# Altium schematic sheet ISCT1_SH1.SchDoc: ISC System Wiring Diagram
size B; DrawnBy: Filiberto Clara; Engineer: Filiberto Clara; Organization: LIGO Laboratory; Address1: California Institute of Technology; Address2: Massachusetts Institute of Technology; SheetNumber: 24; SheetTotal: 39
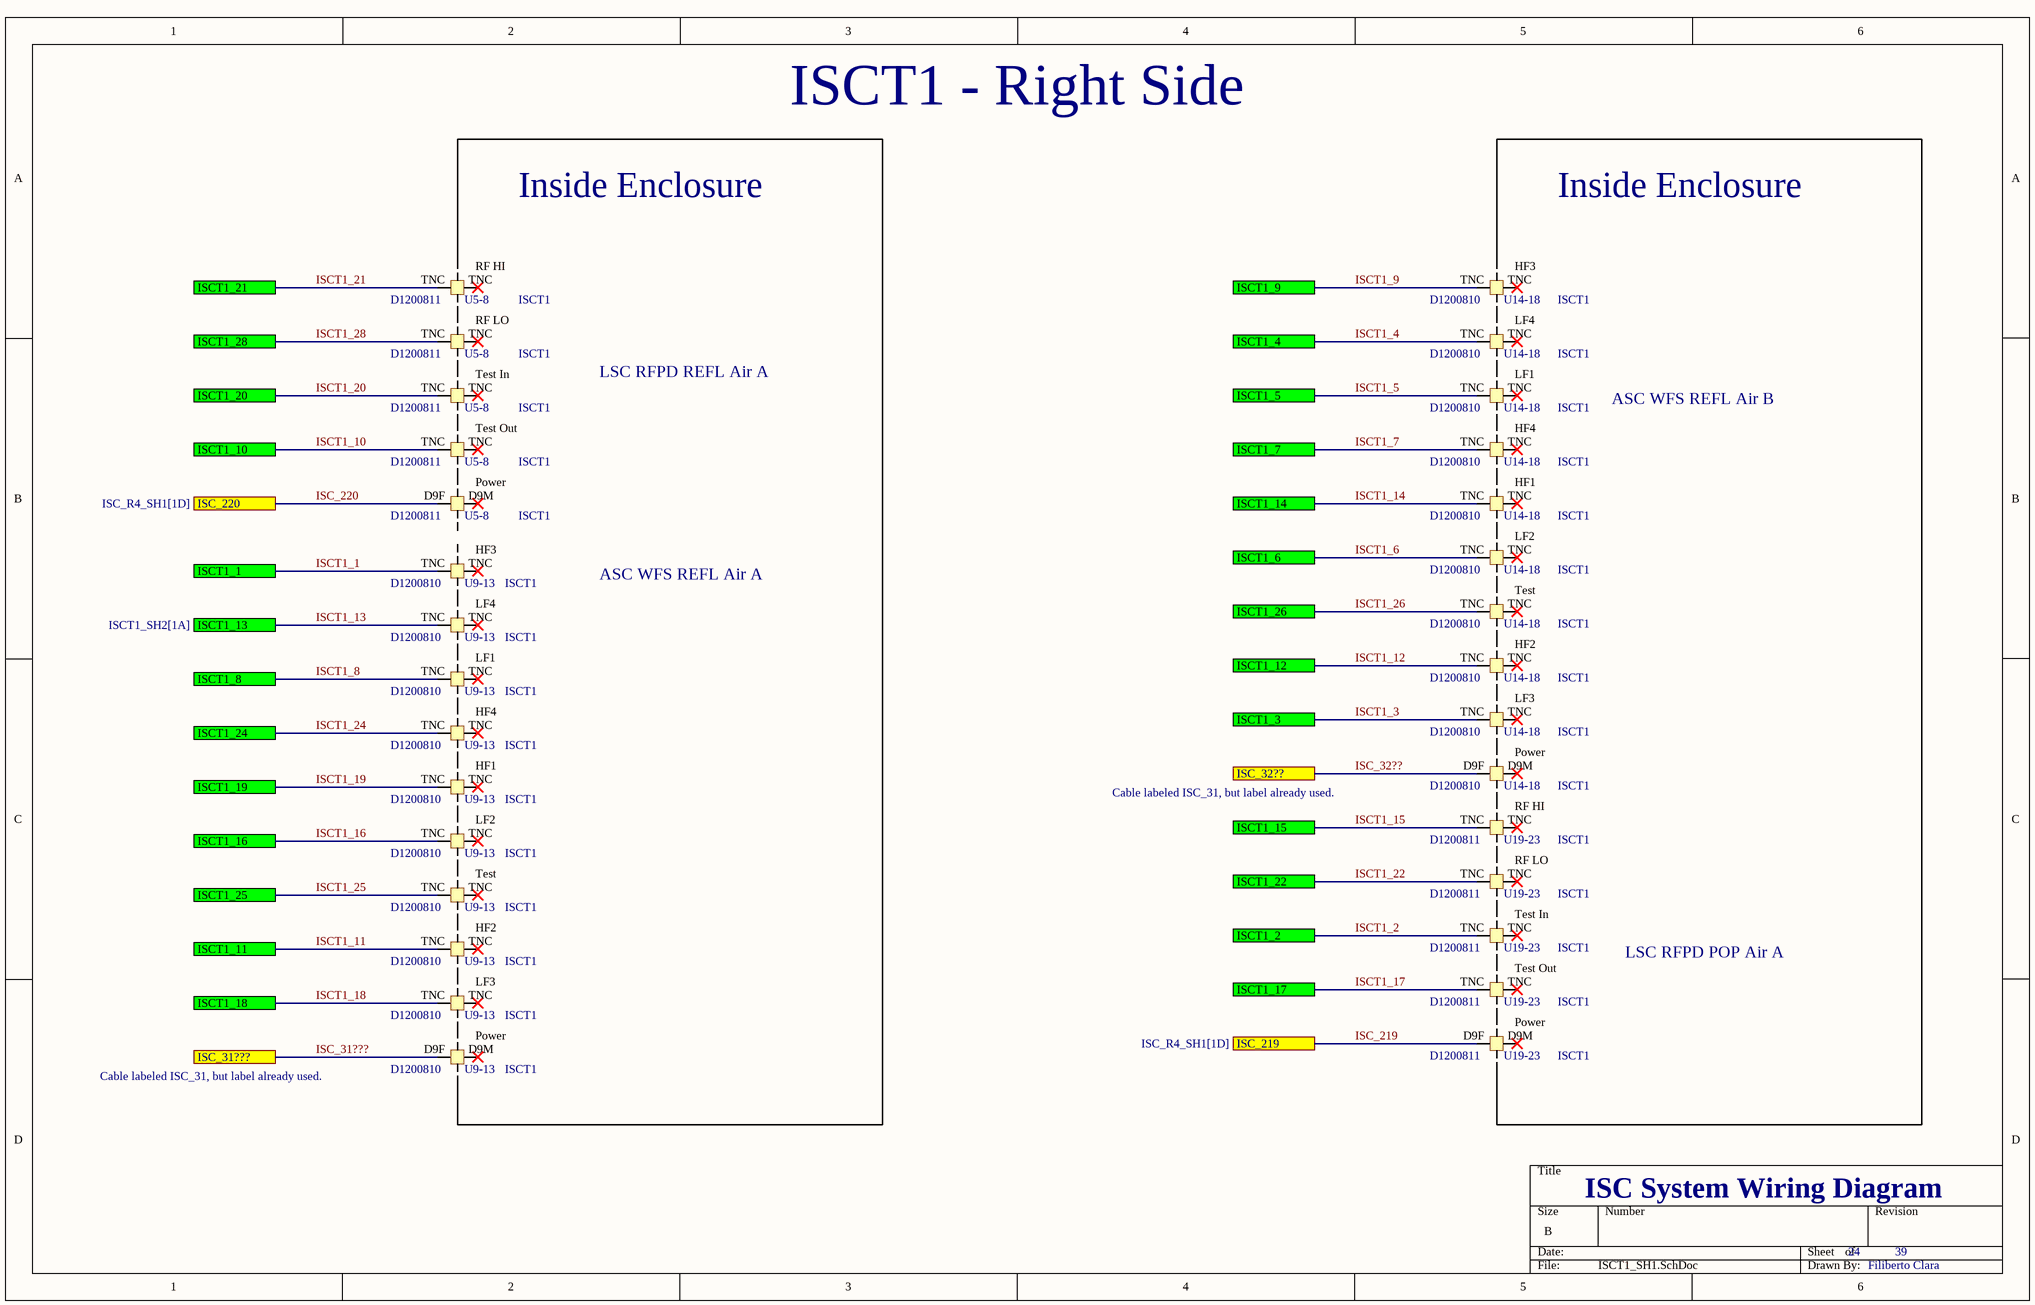
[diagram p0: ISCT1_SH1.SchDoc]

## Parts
C_ISCT1_1  DCC: D1200811  Rack: ISCT1  Slot: U5-8  (hidden comment: Patch Panel Dual Frequency LSC RFPD)  (parts A,B,C,D,E of 5)
C_ISCT1_2  DCC: D1200810  Rack: ISCT1  Slot: U9-13  (hidden comment: Patch Panel Dual Frequency WFS RFPD)  (parts A,B,C,D,E,F,G,H,I,J of 10)
C_ISCT1_3  DCC: D1200810  Rack: ISCT1  Slot: U14-18  (hidden comment: Patch Panel Dual Frequency WFS RFPD)  (parts A,B,C,D,E,F,G,H,I,J of 10)
C_ISCT1_4  DCC: D1200811  Rack: ISCT1  Slot: U19-23  (hidden comment: Patch Panel Dual Frequency LSC RFPD)  (parts A,B,C,D,E of 5)

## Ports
ISC_31???, ISC_32??, ISC_219 (see ISC_R4_SH1[1D]), ISC_220 (see ISC_R4_SH1[1D]), ISCT1_1, ISCT1_2, ISCT1_3, ISCT1_4, ISCT1_5, ISCT1_6, ISCT1_7, ISCT1_8, ISCT1_9, ISCT1_10, ISCT1_11, ISCT1_12, ISCT1_13 (see ISCT1_SH2[1A]), ISCT1_14, ISCT1_15, ISCT1_16, ISCT1_17, ISCT1_18, ISCT1_19, ISCT1_20, ISCT1_21, ISCT1_22, ISCT1_24, ISCT1_25, ISCT1_26, ISCT1_28

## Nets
ISC_31???: C_ISCT1_2.D9F(Power) ; port ISC_31???
ISC_32??: C_ISCT1_3.D9F(Power) ; port ISC_32??
ISC_219: C_ISCT1_4.D9F(Power) ; port ISC_219
ISC_220: C_ISCT1_1.D9F(Power) ; port ISC_220
ISCT1_1: C_ISCT1_2.TNC(H3F) ; port ISCT1_1
ISCT1_2: C_ISCT1_4.TNC(TestIn) ; port ISCT1_2
ISCT1_3: C_ISCT1_3.TNC(LF3) ; port ISCT1_3
ISCT1_4: C_ISCT1_3.TNC(LF4) ; port ISCT1_4
ISCT1_5: C_ISCT1_3.TNC(LF1) ; port ISCT1_5
ISCT1_6: C_ISCT1_3.TNC(LF2) ; port ISCT1_6
ISCT1_7: C_ISCT1_3.TNC(HF4) ; port ISCT1_7
ISCT1_8: C_ISCT1_2.TNC(LF1) ; port ISCT1_8
ISCT1_9: C_ISCT1_3.TNC(H3F) ; port ISCT1_9
ISCT1_10: C_ISCT1_1.TNC(TestOut) ; port ISCT1_10
ISCT1_11: C_ISCT1_2.TNC(HF2) ; port ISCT1_11
ISCT1_12: C_ISCT1_3.TNC(HF2) ; port ISCT1_12
ISCT1_13: C_ISCT1_2.TNC(LF4) ; port ISCT1_13
ISCT1_14: C_ISCT1_3.TNC(HF1) ; port ISCT1_14
ISCT1_15: C_ISCT1_4.TNC(RFHI) ; port ISCT1_15
ISCT1_16: C_ISCT1_2.TNC(LF2) ; port ISCT1_16
ISCT1_17: C_ISCT1_4.TNC(TestOut) ; port ISCT1_17
ISCT1_18: C_ISCT1_2.TNC(LF3) ; port ISCT1_18
ISCT1_19: C_ISCT1_2.TNC(HF1) ; port ISCT1_19
ISCT1_20: C_ISCT1_1.TNC(TestIn) ; port ISCT1_20
ISCT1_21: C_ISCT1_1.TNC(RFHI) ; port ISCT1_21
ISCT1_22: C_ISCT1_4.TNC(RFLO) ; port ISCT1_22
ISCT1_24: C_ISCT1_2.TNC(HF4) ; port ISCT1_24
ISCT1_25: C_ISCT1_2.TNC(Test) ; port ISCT1_25
ISCT1_26: C_ISCT1_3.TNC(Test) ; port ISCT1_26
ISCT1_28: C_ISCT1_1.TNC(RFLO) ; port ISCT1_28

Not connected (* = marked no-connect by the designer): C_ISCT1_1 D9M(Power)*; C_ISCT1_2 D9M(Power)*; C_ISCT1_3 D9M(Power)*; C_ISCT1_4 D9M(Power)*

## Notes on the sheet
- ISCT1 - Right Side
- Inside Enclosure
- LSC RFPD REFL Air A
- ASC WFS REFL Air B
- ASC WFS REFL Air A
- Cable labeled ISC_31, but label already used.
- LSC RFPD POP Air A

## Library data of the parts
C_ISCT1_1 C_ISCT1_4 = Patch Panel Dual Frequency LSC RFPD: Patch Panel (D1200811); Serial: Sxxxxxxx; System: ISC
C_ISCT1_2 C_ISCT1_3 = Patch Panel Dual Frequency WFS RFPD: Patch Panel (D1200810); Serial: Sxxxxxxx; System: ISC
